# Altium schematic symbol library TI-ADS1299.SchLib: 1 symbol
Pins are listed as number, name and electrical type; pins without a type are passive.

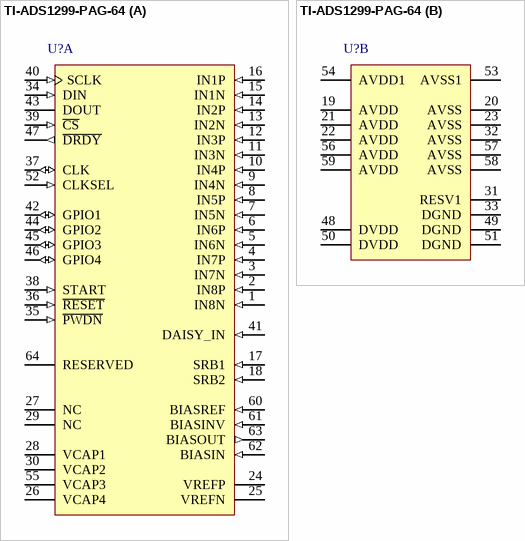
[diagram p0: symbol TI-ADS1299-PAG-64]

## TI-ADS1299-PAG-64
designator U?
The Famous ADS1299 :)
footprint TI-PAG64_N (QFP, 64-Leads, Body 10x10mm, Pitch 0.5mm, IPC Medium Density)
footprint TI-PAG64_N (QFP, 64-Leads, Body 10x10mm, Pitch 0.5mm, IPC Medium Density)
footprint TI-PAG64_N (QFP, 64-Leads, Body 10x10mm, Pitch 0.5mm, IPC Medium Density)
part A pins: 1 IN8N (in) "Differential analog negative input 8", 2 IN8P (in) "Differential analog positive input 8", 3 IN7N (in) "Differential analog negative input 7", 4 IN7P (in) "Differential analog positive input 7", 5 IN6N (in) "Differential analog negative input 6", 6 IN6P (in) "Differential analog positive input 6", 7 IN5N (in) "Differential analog negative input 5", 8 IN5P (in) "Differential analog positive input 5", 9 IN4N (in) "Differential analog negative input 4", 10 IN4P (in) "Differential analog positive input 4", 11 IN3N (in) "Differential analog negative input 3", 12 IN3P (in) "Differential analog positive input 3", 13 IN2N (in) "Differential analog negative input 2", 14 IN2P (in) "Differential analog positive input 2", 15 IN1N (in) "Differential analog negative input 1", 16 IN1P (in) "Differential analog positive input 1", 17 SRB1 (in) "Patient stimulus, reference, and bias signal 1", 18 SRB2 (in) "Patient stimulus, reference, and bias signal 2", 24 VREFP "Positive reference voltage", 25 VREFN "Negative reference voltage", 26 VCAP4 "Analog bypass capacitor", 27 NC "No connection", 28 VCAP1 "Analog bypass capacitor", 29 NC "No connection", 30 VCAP2 "Analog bypass capacitor", 34 DIN (in) "SPI data in", 35 ~{PWDN} (in) "Power-down; active low", 36 ~{RESET} (in) "System reset; active low", 37 CLK (io) "Master clock input", 38 START (in) "Start conversion", 39 ~{CS} (in) "SPI chip select; active low", 40 SCLK (in) "SPI clock", 41 DAISY_IN (in) "Daisy-chain input", 42 GPIO1 (io) "General-purpose input/output pin", 43 DOUT (hiz) "SPI data out", 44 GPIO2 (io) "General-purpose input/output pin", 45 GPIO3 (io) "GPIO3 in normal mode", 46 GPIO4 (io) "GPIO4 in normal mode", 47 ~{DRDY} (out) "Data ready; active low", 52 CLKSEL (in) "Master clock select", 55 VCAP3 "Analog bypass capacitor", 60 BIASREF (in) "Bias drive noninverting input", 61 BIASINV (in) "Bias drive inverting input", 62 BIASIN (in) "Bias drive input to MUX", 63 BIASOUT (out) "Bias drive output", 64 RESERVED "Leave as open circuit"
part B pins: 19 AVDD (power) "Analog supply", 20 AVSS (power) "Analog ground", 21 AVDD (power) "Analog supply", 22 AVDD (power) "Analog supply", 23 AVSS (power) "Analog ground", 31 RESV1 (power) "Reserved for future use. Must tie to logic low (DGND)", 32 AVSS (power) "Analog ground", 33 DGND (power) "Digital ground", 48 DVDD (power) "Digital power supply", 49 DGND (power) "Digital ground", 50 DVDD (power) "Digital power supply", 51 DGND (power) "Digital ground", 53 AVSS1 (power) "Analog ground", 54 AVDD1 (power) "Analog supply", 56 AVDD (power) "Analog supply", 57 AVSS (power) "Analog ground", 58 AVSS (power) "Charge pump analog ground", 59 AVDD (power) "Charge pump analog supply"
